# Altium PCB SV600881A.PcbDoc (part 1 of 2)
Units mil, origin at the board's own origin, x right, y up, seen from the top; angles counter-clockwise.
Board outline 3700 x 3510 mil, 4 copper layers (Top Layer, MidLayer1, MidLayer2, Bottom Layer), stack 62.2 mil thick; 110 components, 46 nets, 261 pads, 195 vias.
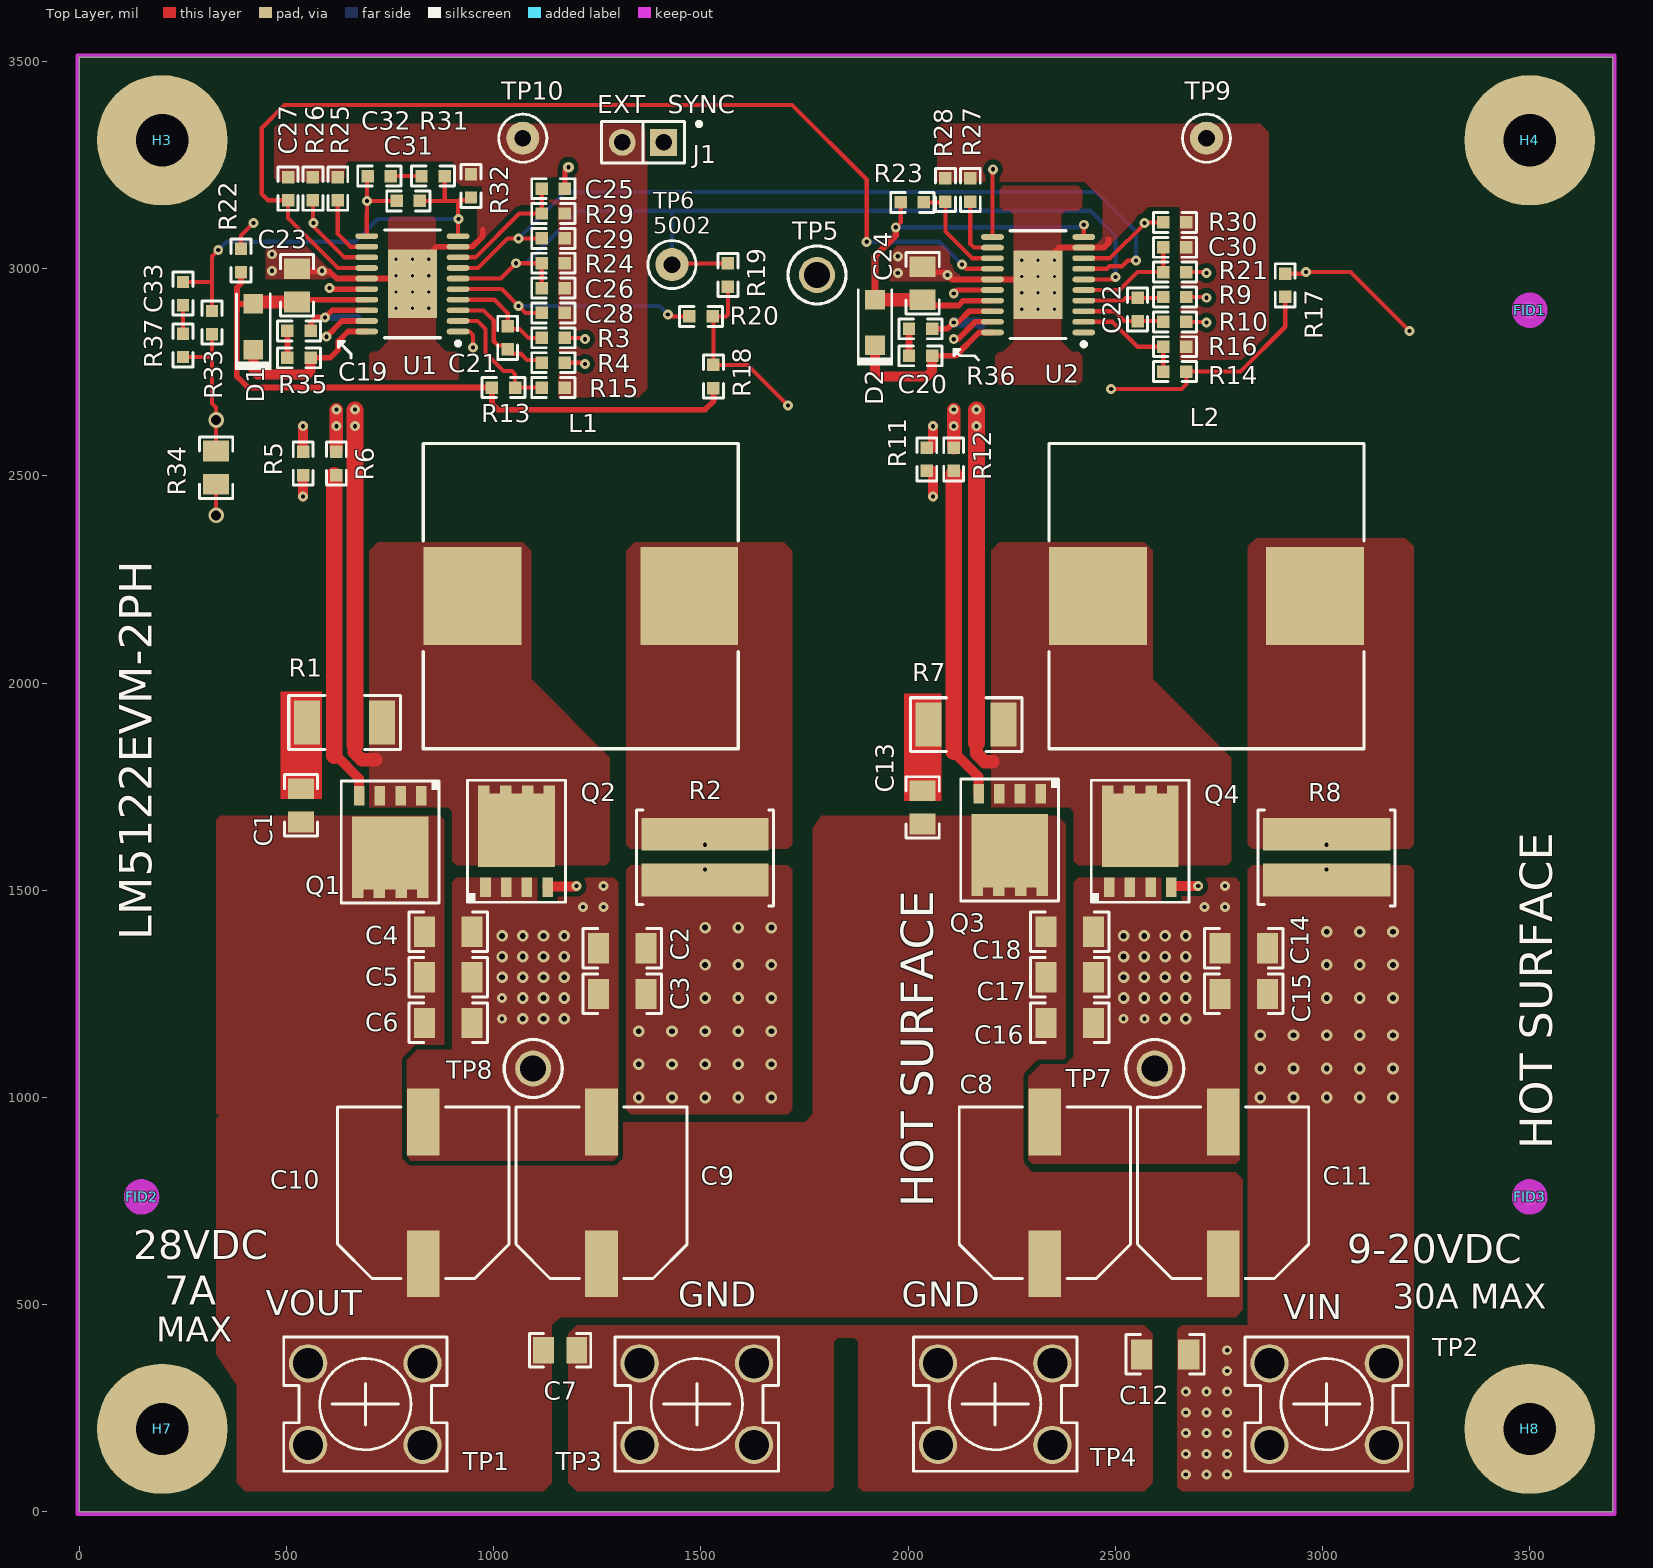
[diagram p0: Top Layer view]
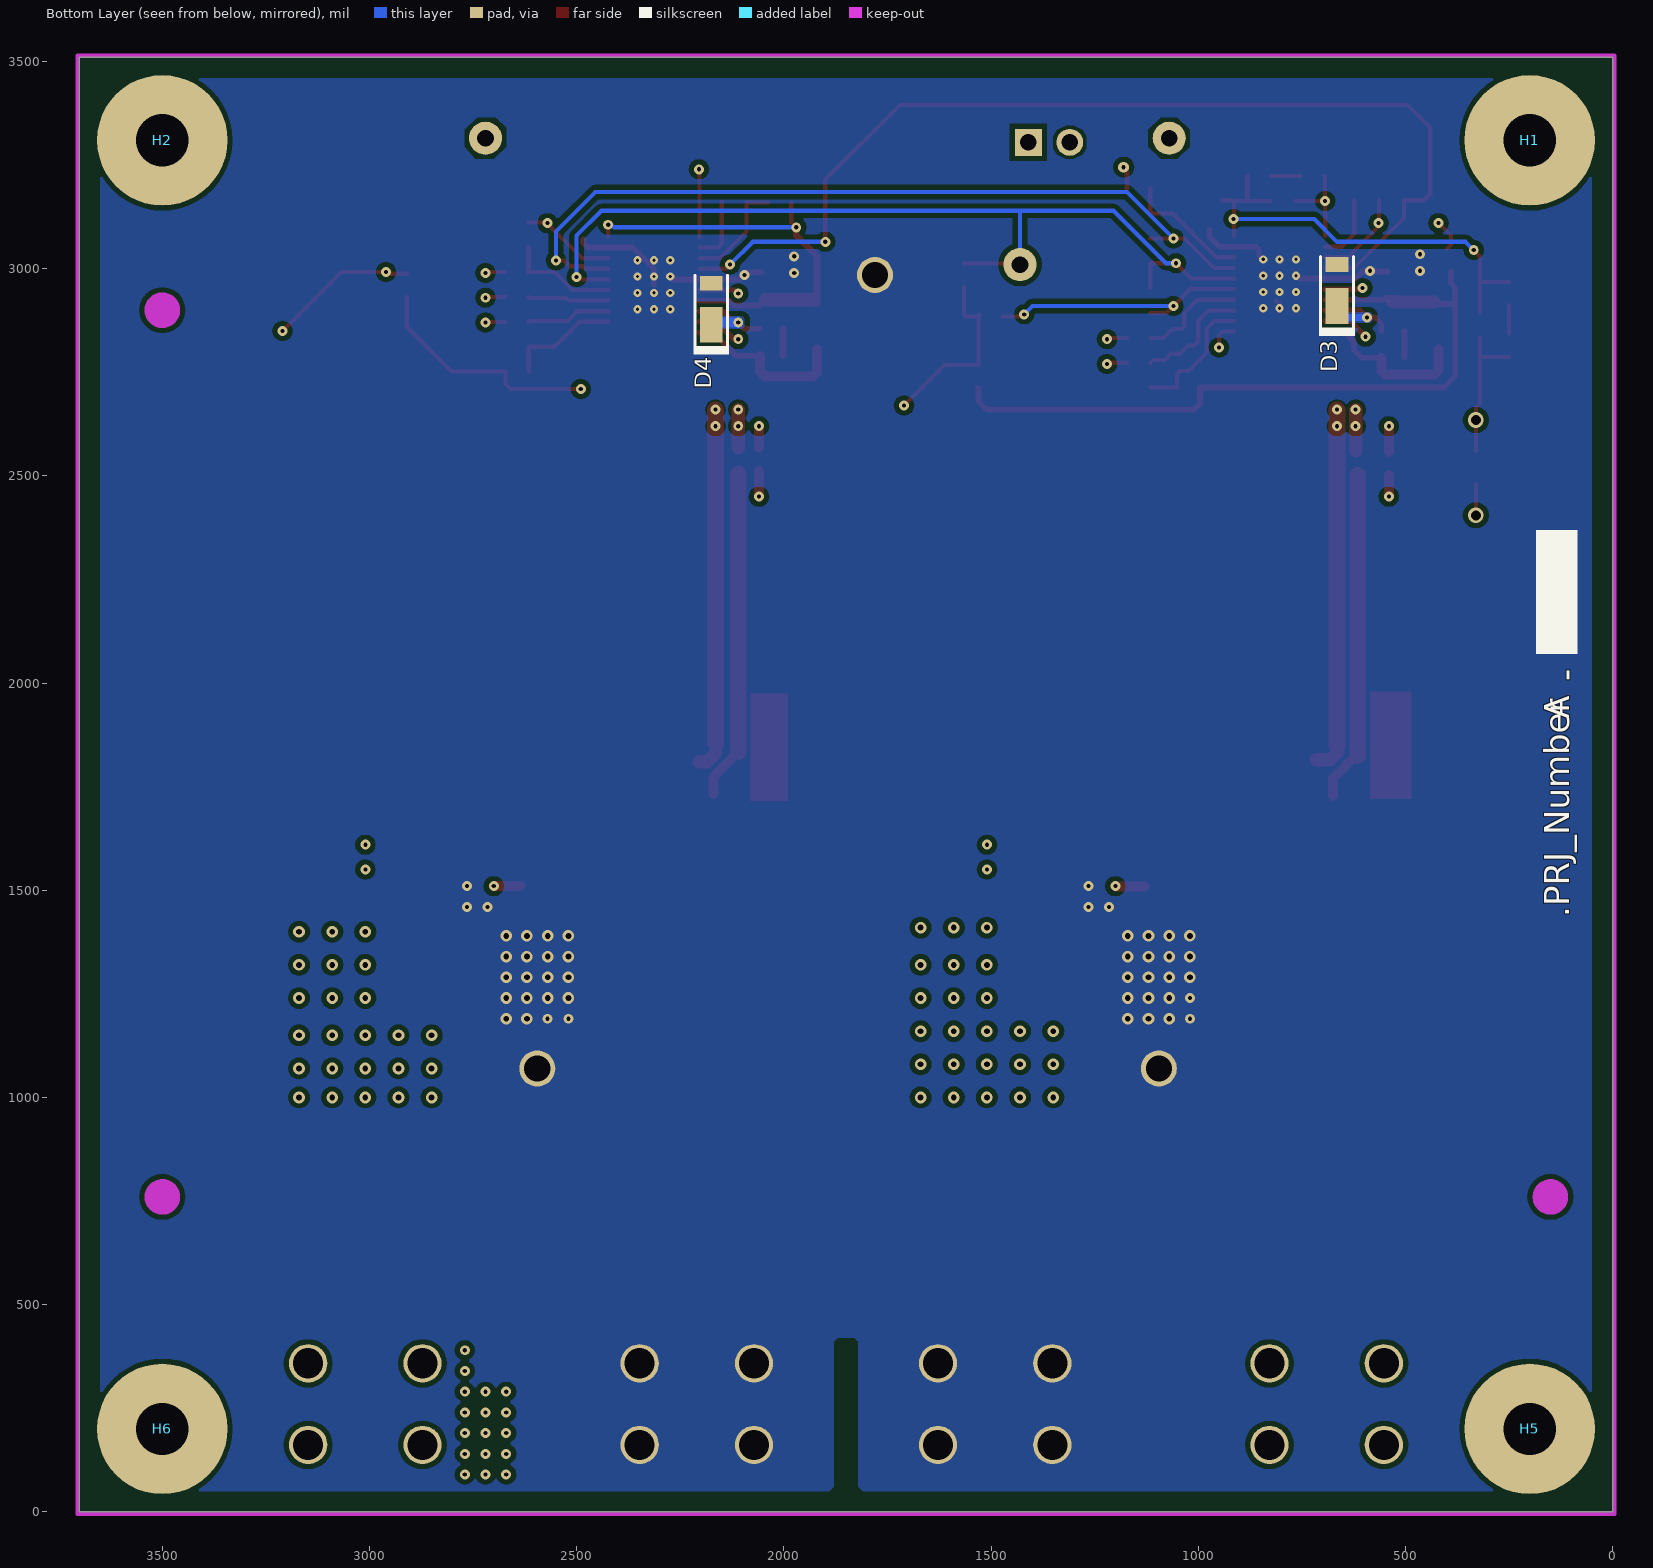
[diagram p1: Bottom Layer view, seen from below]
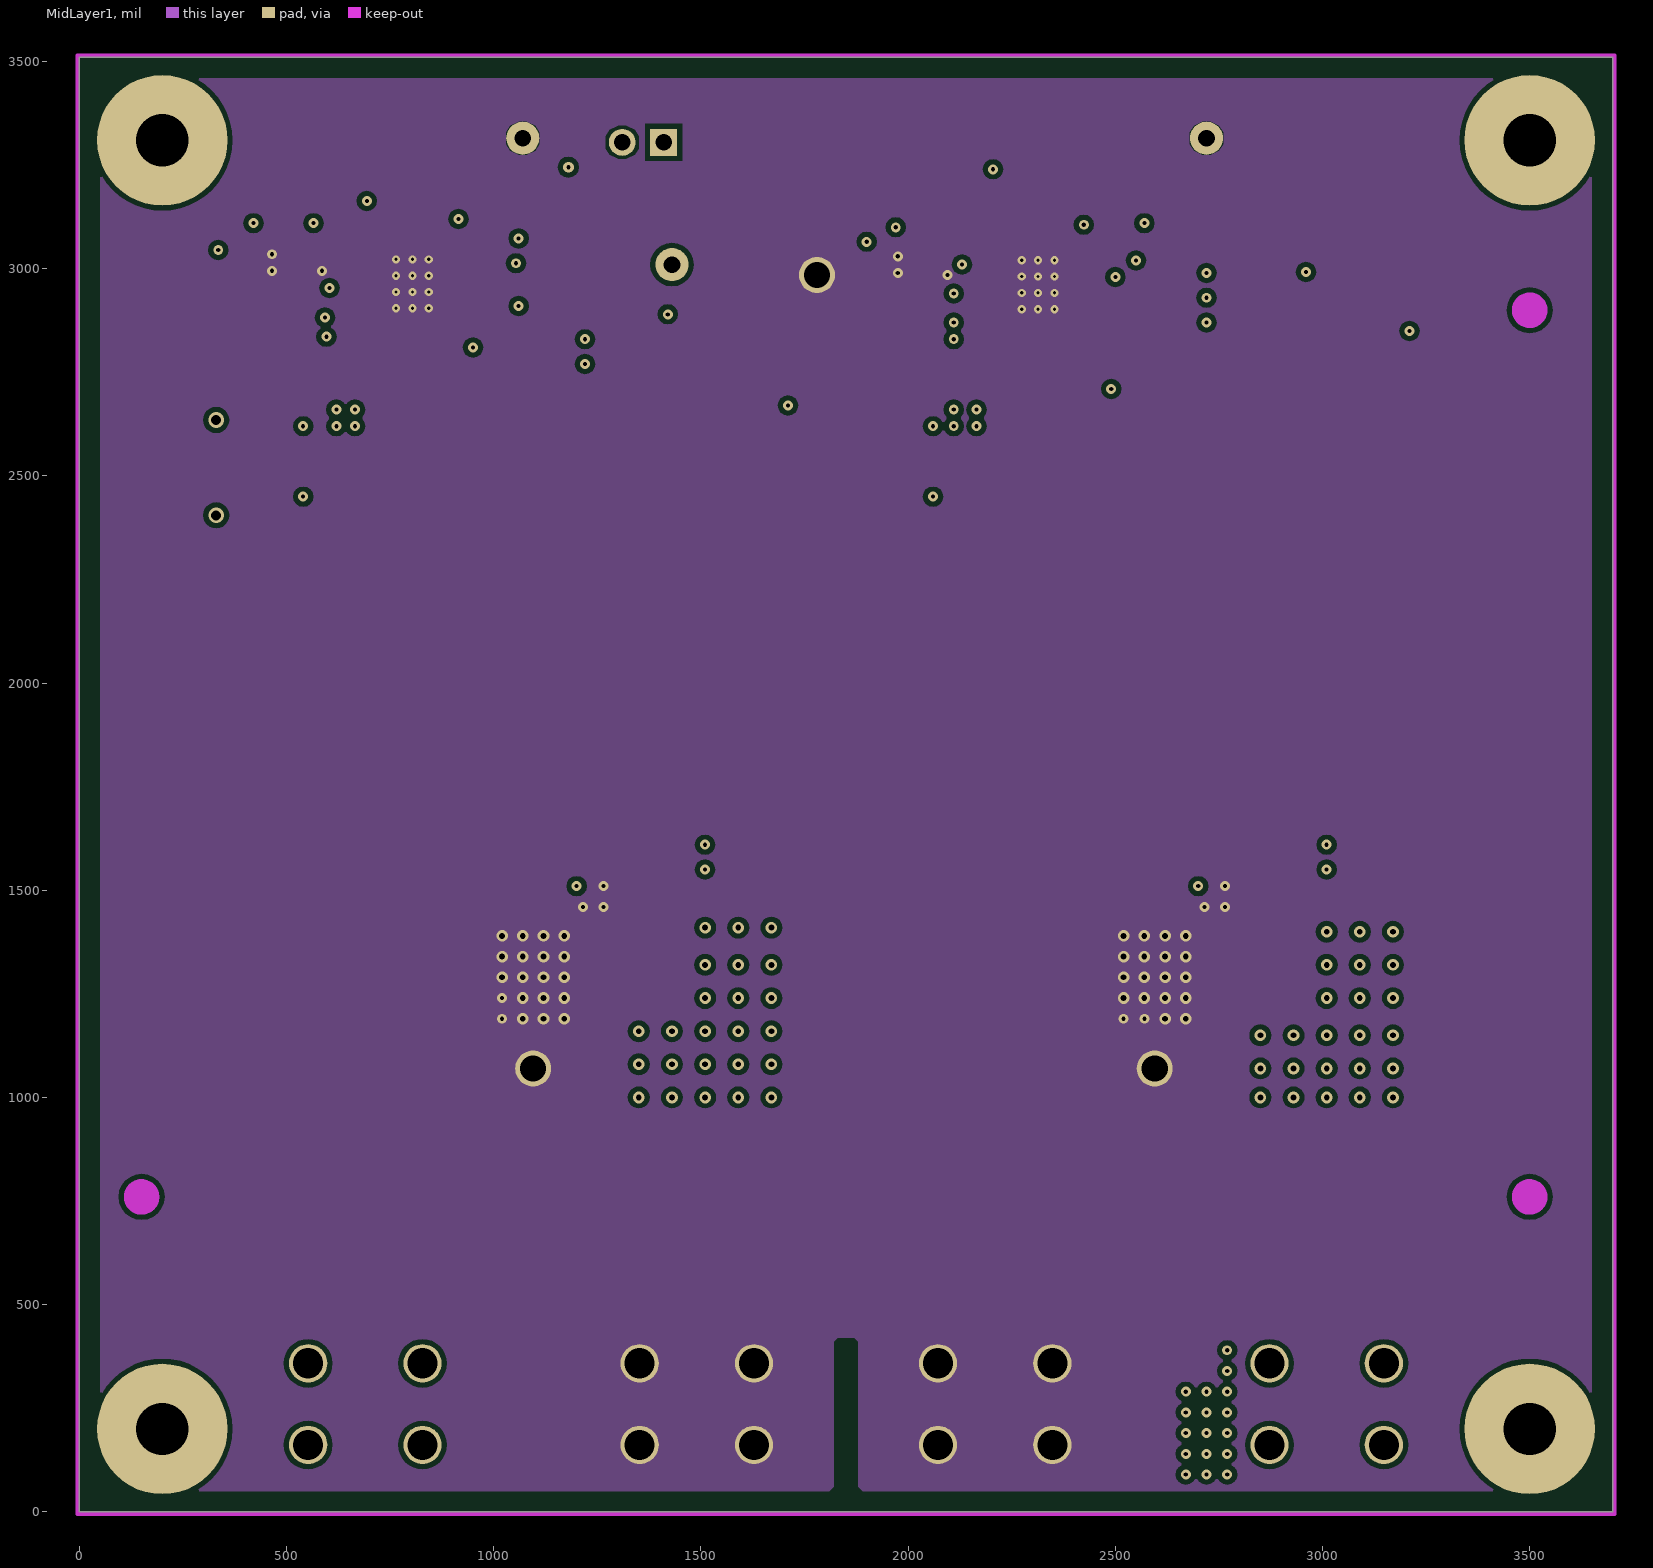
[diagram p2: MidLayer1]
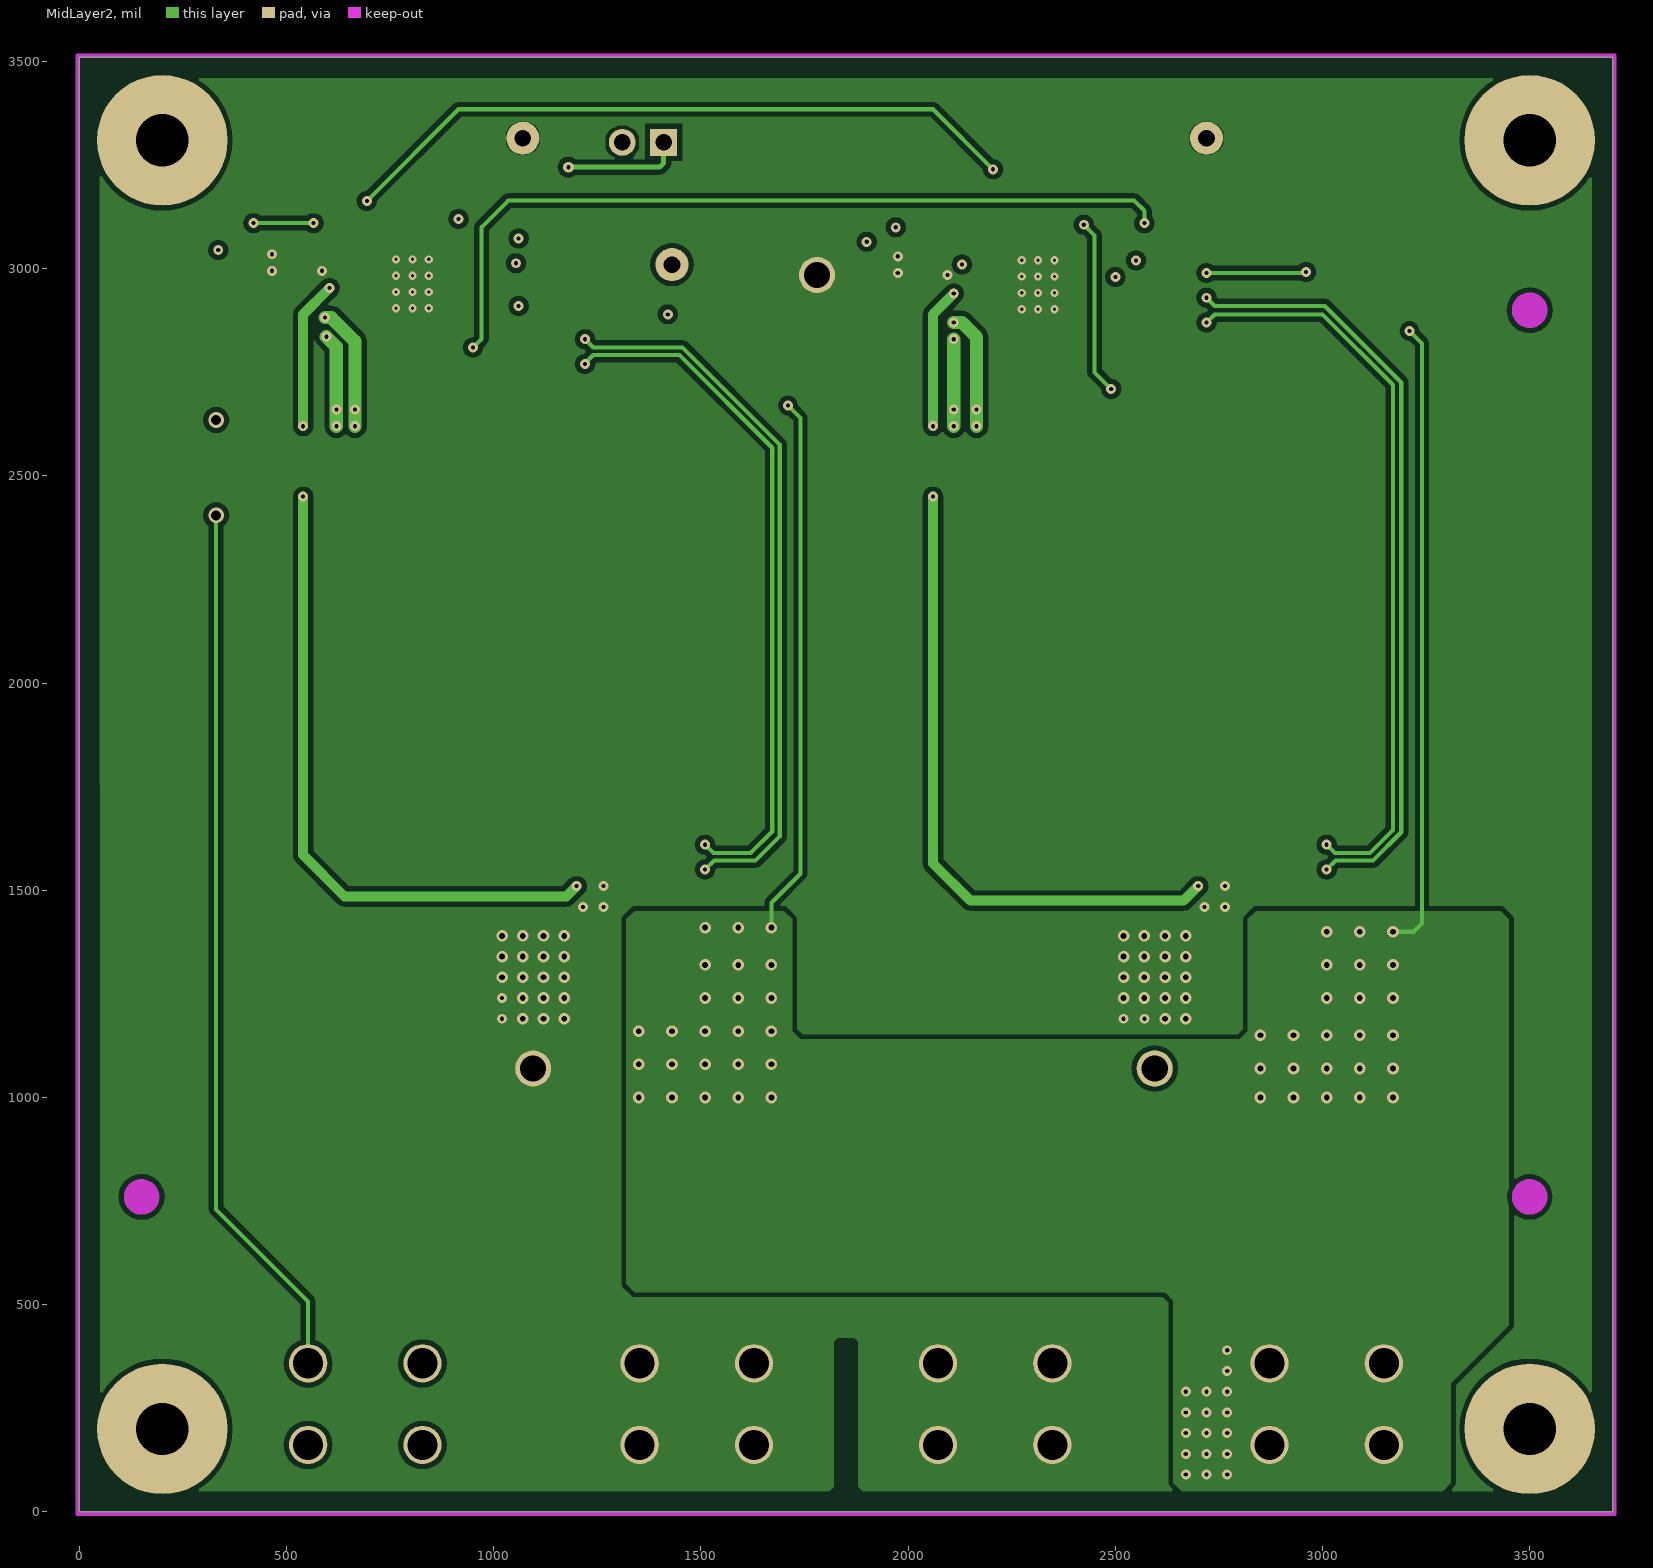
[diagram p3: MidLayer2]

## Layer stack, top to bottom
Top Solder: solder mask 0.4, Solder Resist, Dk 3.5
Top Layer: signal copper 2.8
Dielectric1: core 17, FR-4, Dk 4.8
MidLayer1: signal copper 2.8
Dielectric2: prepreg 17, FR-4, Dk 4.8
MidLayer2: signal copper 2.8
Dielectric3: core 17, FR-4, Dk 4.8
Bottom Layer: signal copper 2.8
Bottom Solder: solder mask 0.4, Solder Resist, Dk 3.5

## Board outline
0,0 0,3510 3700,3510 3700,0

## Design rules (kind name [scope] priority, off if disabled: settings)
AcuteAngle [All] p1: minimum=4.50000000000000E+0001 checktracksonly=FALSE
AssemblyTestPointUsage [All] p1: valid=2
Clearance Clearance_1 [IsRegion] p1: gap=12 ignorepadtopadclearanceinfootprint=FALSE except(0: Arc-Hole Track-Hole SMDPad-Hole THPad-Hole Via-Hole Fill-Hole Poly-Hole Region-Hole Text-Hole)
Clearance Clearance_BoardEdge_MountingHoles [OnCopper and InComponentClass('Mounting Holes') vs IsKeepOut] p2: gap=40 ignorepadtopadclearanceinfootprint=FALSE except(0: Arc-Hole Track-Hole SMDPad-Hole THPad-Hole Via-Hole Fill-Hole Poly-Hole Region-Hole Text-Hole)
Clearance Clearance_BoardEdge_Poly [OnCopper and InPoly vs IsKeepOut] p3: gap=25 ignorepadtopadclearanceinfootprint=FALSE except(0: Arc-Hole Track-Hole SMDPad-Hole THPad-Hole Via-Hole Fill-Hole Poly-Hole Region-Hole Text-Hole)
Clearance Clearance_BoardEdge [OnCopper and Not InComponentClass('Logo') and not InComponentClass('FiducialMark') and not InRegion(1000,500,4000,800) vs IsKeepOut] p4: gap=75 ignorepadtopadclearanceinfootprint=FALSE except(0: Arc-Hole Track-Hole SMDPad-Hole THPad-Hole Via-Hole Fill-Hole Poly-Hole Region-Hole Text-Hole)
Clearance [All] p5: gap=8 ignorepadtopadclearanceinfootprint=FALSE except(0: Arc-Hole Track-Hole SMDPad-Hole THPad-Hole Via-Hole Fill-Hole Poly-Hole Region-Hole Text-Hole)
ComponentClearance ComponentVOCap [HasFootprint('SM_RADIAL_G')] p1: gap=10 collisioncheckmode=3 verticalgap=10 showdistances=FALSE
ComponentClearance ComponentClearance_Logo [InComponentClass(Logo)] p2: gap=50 collisioncheckmode=3 verticalgap=10 showdistances=FALSE
ComponentClearance ComponentClearance_ScrewToNut [(HasFootprint('NY PMS 440 0025 PH')) vs (HasFootprint('Keystone_1902C'))] p3: gap=5 collisioncheckmode=3 verticalgap=10 showdistances=FALSE
ComponentClearance ComponentClearance_MountingHoles [InComponentClass('Mounting Holes')] p4: gap=150 collisioncheckmode=3 verticalgap=200 showdistances=FALSE
ComponentClearance ComponentClearance_SmallPassives [HasFootprint('0201*') or HasFootprint('0402*') or HasFootprint('0508') or HasFootprint('0603*') or HasFootprint('0612') or HasFootprint('0805*') or HasFootprint('0815*') or HasFootprint('0830*') or HasFootprint('1206*') or HasFootprint('1210*') or HasFootprint('1808*') or HasFootprint('1812*') or HasFootprint('1825*') or HasFootprint('2010*') or HasFootprint('2220*') or HasFootprint('2225*') or HasFootprint('2512*') or HasFootprint('2728*') or HasFootprint('3518*') vs HasFootprint('0201*') or HasFootprint('0402*') or HasFootprint('0508') or HasFootprint('0603*') or HasFootprint('0612') or HasFootprint('0805*') or HasFootprint('0815*') or HasFootprint('0830*') or HasFootprint('1206*') or HasFootprint('1210*') or HasFootprint('1808*') or HasFootprint('1812*') or HasFootprint('1825*') or HasFootprint('2010*') or HasFootprint('2220*') or HasFootprint('2225*') or HasFootprint('2512*') or HasFootprint('2728*') or HasFootprint('3518*')] p5: gap=20 collisioncheckmode=3 verticalgap=10 showdistances=FALSE
ComponentClearance ComponentClearance_THtoSMT [IsThruComponent vs IsSMTComponent] p6: gap=60 collisioncheckmode=3 verticalgap=60 showdistances=FALSE
ComponentClearance ComponentClearance_THtoTH [IsThruComponent vs IsThruComponent] p7: gap=60 collisioncheckmode=3 verticalgap=60 showdistances=FALSE
ComponentClearance [All] p8: gap=40 collisioncheckmode=3 verticalgap=10 showdistances=FALSE
DiffPairsRouting [All] p1: maxlimit=100 minlimit=10 mostfreqgap=10 toplayer_minwidth=15 toplayer_maxwidth=15 toplayer_prefwidth=15 midlayer1_minwidth=15 midlayer1_maxwidth=15 midlayer1_prefwidth=15 midlayer2_minwidth=15 midlayer2_maxwidth=15 midlayer2_prefwidth=15 bottomlayer_minwidth=15 bottomlayer_maxwidth=15 bottomlayer_prefwidth=15 maxuncoupledlength=1000
FabricationTestPointUsage TestPointUsage [All] p1: valid=2 allowmultiple=FALSE
FabricationTestpoint Testpoint [All] p1: side=3 testpointundercomponent=TRUE minsize=40 maxsize=100 preferedsize=60 minholesize=0 maxholesize=40 preferedholesize=32 testpointgrid=1 allowsidetop=TRUE allowsidebottom=TRUE usegrid=TRUE gridtolerance=0.01
FanoutControl Fanout_LCC [IsLCC] p1: bgadir=Out bgaviamode=Centered fanoutstyle=Auto fanoutdirection=Alternating viagrid=1 // Fanout_LCC (Default Rule)
FanoutControl Fanout_BGA [IsBGA] p2: bgadir=Out bgaviamode=Centered fanoutstyle=Auto fanoutdirection=Alternating viagrid=1 // Fanout_BGA (Default Rule)
FanoutControl Fanout_Default [All] p4: bgadir=Out bgaviamode=Centered fanoutstyle=Auto fanoutdirection=Alternating viagrid=1 // Fanout_Default (Default Rule)
FanoutControl Fanout_Small [(CompPinCount < 5)] p5: bgadir=Out bgaviamode=Centered fanoutstyle=Auto fanoutdirection=OutThenIn viagrid=1 // Fanout_Small (Default Rule)
HoleSize [All] p1: absolutevalues=TRUE maxlimit=251 minlimit=7.87 maxpercent=80.000 minpercent=20.000
MinimumAnnularRing MinimumAnnularRing_1 [HasFootprint('MXA20A_L')] p1: minimumring=5
MinimumAnnularRing [All] p2: minimumring=7
MinimumSolderMaskSliver MinimumSolderMaskSliver_Logo [InComponentClass('Logo') vs InComponentClass('Logo')] p1: minsoldermaskwidth=0.7
MinimumSolderMaskSliver [All] p2: minsoldermaskwidth=4
PlaneClearance PolygonClearance_1 [IsRegion] p1: clearance=10
PlaneClearance [All] p2: clearance=10
PlaneConnect [All] p1: planeconnectstyle=Relief reliefexpansion=10 reliefentries=4 reliefconductorwidth=10 reliefairgap=10
PolygonConnect [All] p1: connectstyle=Direct reliefconductorwidth=10 reliefentries=4 polygonreliefangle="90 Angle" airgapwidth=10
RoutingVias [All] p1: holewidth=10 width=24 viastyle="Through Hole" minholewidth=7 minwidth=14 maxholewidth=40 maxwidth=65
SMDToCorner [All] p1: distance=30000
SilkToSilkClearance [All] p1: silktosilkclearance=5
SilkToSolderMaskClearance SilkscreenOverComponentPads [IsPad] p1: minsilkscreentomaskgap=5 clearancetoexposedcopper=TRUE
SolderMaskExpansion [All] p1: expansion=3
Width [All] p1: maxlimit=100 minlimit=6 preferedwidth=10 checkconnectedcopper=TRUE
15 further rules are at their usual default settings.

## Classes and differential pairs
component class SV600881A_SH2: C19 C20 C21 C22 C23 C24 C25 C26 C27 C28 C29 C30 C31 C32 C33 D1 D2 D3 D4 J1 R13 R14 R15 R16 R17 R18 R19 R20 R21 R22 R23 R24 R25 R26 R27 R28 R29 R30 R31 R32 R33 R34 R35 R36 R37 TP5 TP6 TP9 TP10 U1 U2
component class SV600881A_SH1: C1 C2 C3 C4 C5 C6 C7 C8 C9 C10 C11 C12 C13 C14 C15 C16 C17 C18 L1 L2 Q1 Q2 Q3 Q4 R1 R2 R3 R4 R5 R6 R7 R8 R9 R10 R11 R12 SH1 TP1 TP2 TP3 TP4 TP7 TP8
component class FiducialMark: FID1 FID2 FID3
component class SV600881A_HW: FID1 FID2 FID3 H1 H2 H3 H4 H5 H6 H7 H8 ZZ1 ZZ2 ZZ3 ZZ4 ZZ5 ZZ6
component class "Mounting Holes": H3 H4 H7 H8
component class Header: J1
component class AssemblyNote: ZZ1 ZZ2 ZZ3 ZZ4 ZZ5 ZZ6

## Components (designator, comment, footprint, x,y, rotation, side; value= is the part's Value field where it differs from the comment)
C1 "GRM2165C2A471JA01D" 0805_HV 535,1705 r90 top value=470pF
C2 "3.3µF" 1206 1310,1360 r180 top
C3 "3.3µF" 1206 1310,1250 r180 top
C4 "10µF" 1206 890,1400 r0 top
C5 "10µF" 1206 890,1290 r0 top
C6 "10µF" 1206 890,1180 r0 top
C7 "GRM21BR71H105KA12L" 0805_HV 1160,390 r0 top value=1uF
C8 "EEE-FP1V331AP" SM_RADIAL_G 2330,770 r90 top value=330uF
C9 "EEE-FP1V331AP" SM_RADIAL_G 1260,770 r90 top value=330uF
C10 "EEE-FP1V331AP" SM_RADIAL_G 830,770 r90 top value=330uF
C11 "EEE-FP1V331AP" SM_RADIAL_G 2760,770 r90 top value=330uF
C12 "3.3µF" 1206 2620,380 r180 top
C13 "GRM2165C2A471JA01D" 0805_HV 2035,1700 r90 top value=470pF
C14 "3.3µF" 1206 2810,1360 r180 top
C15 "3.3µF" 1206 2810,1250 r180 top
C16 "10µF" 1206 2390,1180 r0 top
C17 "10µF" 1206 2390,1290 r0 top
C18 "10µF" 1206 2390,1400 r0 top
C19 "GRM188R71E104KA01D" 0603_HV 530,2785 r0 top value=0.1uF
C20 "GRM188R71E104KA01D" 0603_HV 2030,2790 r0 top value=0.1uF
C21 "GRM1885C1H101JA01D" 0603_HV 1033.6,2833.29 r90 top value=100pF
C22 "GRM1885C1H101JA01D" 0603_HV 2553.62,2901.81 r90 top value=100pF
C23 "GRM21BR71C475KA73L" 0805_HV 525,2960 r270 top value=4.7uF
C24 "GRM21BR71C475KA73L" 0805_HV 2035,2965 r270 top value=4.7uF
C25 "GRM1885C1H101JA01D" 0603_HV 1143.6,3193.29 r0 top value=100pF
C26 "GRM1885C1H101JA01D" 0603_HV 1143.6,2953.29 r0 top value=100pF
C27 "GRM188R71E474KA12D" 0603_HV 503.6,3193.29 r90 top value=0.47uF
C28 "GRM188R71E474KA12D" 0603_HV 1143.6,2893.29 r0 top value=0.47uF
C29 "GRM188R71E104KA01D" 0603_HV 1143.6,3073.29 r0 top value=0.1uF
C30 "GRM188R71E474KA12D" 0603_HV 2643.62,3051.81 r0 top value=0.47uF
C31 "C0603C331K5RACTU" 0603_HV 793.6,3163.6 r180 top value=330pF
C32 "C0603C223K5RACTU" 0603_HV 723.6,3223.6 r180 top value=0.022uF
C33 "NA" 0603_HV 250,2940 r90 top
D1 "PMEG6010CEH,115" SOD-123F 420,2860 r90 top value=0.57V
D2 "PMEG6010CEH,115" SOD-123F 1920,2870 r90 top value=0.57V
D3 "DFLS1100-7" powerDI123 665,2960 r90 bottom value=0.77V
D4 "DFLS1100-7" powerDI123 2175,2915 r90 bottom value=0.77V
FID1 "Fiducial" Fiducial10-20 3500,2900 r0 top
FID2 "Fiducial" Fiducial10-20 150,760 r0 top
FID3 "Fiducial" Fiducial10-20 3500,760 r0 top
H1 "1902C" Keystone_1902C 200,3310 r180 bottom locked
H2 "1902C" Keystone_1902C 3500,3310 r180 bottom locked
H3 "NY PMS 440 0025 PH" "NY PMS 440 0025 PH" 200,3310 r0 top locked
H4 "NY PMS 440 0025 PH" "NY PMS 440 0025 PH" 3500,3310 r0 top locked
H5 "1902C" Keystone_1902C 200,200 r180 bottom locked
H6 "1902C" Keystone_1902C 3500,200 r180 bottom locked
H7 "NY PMS 440 0025 PH" "NY PMS 440 0025 PH" 200,200 r0 top locked
H8 "NY PMS 440 0025 PH" "NY PMS 440 0025 PH" 3500,200 r0 top locked
J1 "TSW-102-07-G-S" TSW-102-07-G-S 1360,3305 r180 top
L1 "10uH" "WE-HCI 1890" 1210,2210 r180 top
L2 "10uH" "WE-HCI 1890" 2720,2210 r180 top
Q1 "PSMN4R0-40YS,115" PG-TDSON-8 750,1616.57 r270 top
Q2 "PSMN4R0-40YS,115" PG-TDSON-8 1055,1618.43 r90 top
Q3 "PSMN4R0-40YS,115" PG-TDSON-8 2245,1621.57 r270 top
Q4 "PSMN4R0-40YS,115" PG-TDSON-8 2560,1618.43 r90 top
R1 "8.2" 2010 640,1905 r180 top
R2 "0.004" KRL7638 1510,1580 r90 top
R3 "CRCW0603100RFKEA" 0603_HV 1143.6,2833.29 r0 top value=100
R4 "CRCW0603100RFKEA" 0603_HV 1143.6,2773.29 r0 top value=100
R5 "ERJ-3GEY0R00V" 0603_HV 540,2530 r90 top value=0
R6 "ERJ-3GEY0R00V" 0603_HV 620,2530 r270 top value=0
R7 "8.2" 2010 2140,1900 r180 top
R8 "0.004" KRL7638 3010,1580 r90 top
R9 "CRCW0603100RFKEA" 0603_HV 2643.62,2931.81 r0 top value=100
R10 "CRCW0603100RFKEA" 0603_HV 2643.62,2871.81 r0 top value=100
R11 "ERJ-3GEY0R00V" 0603_HV 2045,2540 r270 top value=0
R12 "ERJ-3GEY0R00V" 0603_HV 2110,2540 r90 top value=0
R13 "ERJ-3GEY0R00V" 0603_HV 1023.6,2713.29 r180 top value=0
R14 "ERJ-3GEY0R00V" 0603_HV 2643.62,2751.81 r0 top value=0
R15 "ERJ-3GEY0R00V" 0603_HV 1143.6,2713.29 r180 top value=0
R16 "ERJ-3GEY0R00V" 0603_HV 2643.62,2811.81 r180 top value=0
R17 "CRCW06033R30JNEA" 0603_HV 2910,2960 r90 top value=3.3
R18 "CRCW06033R30JNEA" 0603_HV 1530,2740 r270 top value=3.3
R19 "CRCW060349K9FKEA" 0603_HV 1565,2985 r270 top value=49.9k
R20 "CRCW06033R30JNEA" 0603_HV 1500,2885 r0 top value=3.3
R21 "CRCW06033R30JNEA" 0603_HV 2643.62,2991.81 r0 top value=3.3
R22 "ERJ-3GEY0R00V" 0603_HV 390,3020 r270 top value=0
R23 "ERJ-3GEY0R00V" 0603_HV 2010,3160 r180 top value=0
R24 "CRCW06038K06FKEA" 0603_HV 1143.6,3013.29 r180 top value=8.06k
R25 "CRCW060378K7FKEA" 0603_HV 623.6,3193.29 r270 top value=78.7k
R26 "ERJ-3GEY0R00V" 0603_HV 563.6,3193.29 r270 top value=0
R27 "CRCW060378K7FKEA" 0603_HV 2150,3190 r270 top value=78.7k
R28 "ERJ-3GEY0R00V" 0603_HV 2090,3190 r270 top value=0
R29 "CRCW060336K5FKEA" 0603_HV 1143.6,3133.29 r180 top value=36.5k
R30 "CRCW060340K2FKEA" 0603_HV 2643.62,3111.81 r180 top value=40.2k
R31 "CRCW060359K0FKEA" 0603_HV 853.6,3223.6 r180 top value=59.0k
R32 "CRCW06032K26FKEA" 0603_HV 945,3200 r90 top value=2.26k
R33 "CRCW060349K9FKEA" 0603_HV 320,2870 r270 top value=49.9k
R34 "CRCW0805576RFKEA" 0805_HV 330,2520 r90 top value=576
R35 "ERJ-3GEY0R00V" 0603_HV 530,2850 r180 top value=0
R36 "ERJ-3GEY0R00V" 0603_HV 2030,2855 r180 top value=0
R37 "NA" 0603_HV 250,2815 r270 top
TP1 "7693" 7693 690,260 r270 top value=15A
TP2 "7693" 7693 3010,260 r270 top value=15A
TP3 "7693" 7693 1490,260 r270 top value=15A
TP4 "7693" 7693 2210,260 r270 top value=15A
TP5 "5011" Keystone5011 1780,2985 r90 top value=Black
TP6 "5002" Keystone5002 1430,3010 r90 top value=White
TP7 "5011" Keystone5011 2595,1070 r0 top value=Black
TP8 "5011" Keystone5011 1095,1070 r90 top value=Black
TP9 "5001" Keystone5001 2720,3315 r90 top value=Black
TP10 "5001" Keystone5001 1070,3315 r90 top value=Black
U1 "LM5122MH" MXA20A_L 803.6,2963.6 r180 top
U2 "LM5122MH" MXA20A_L 2313.62,2961.5 r180 top
ZZ1 "ASSEMBLY NOTES:" AssemblyNoteLabel 4790,3480 r0 top
ZZ2 "These assemblies must be clean and free from flux and all contaminents.  Use of no clean flux is not acceptable." AssemblyNote 4790,3127.8 r0 top
ZZ3 "These Assemblies are ESD sensitive,  ESD precautions shall be observed." AssemblyNote 4790,3293.74 r0 top
ZZ4 "These assemblies must comply with workmanship standards IPC-A-610 class 2, unless otherwise specified." AssemblyNote 4790,2961.87 r0 top
ZZ5 "Standoffs shall be mounted on the bottom side of the assembly." AssemblyNote 4790,2795.93 r0 top
ZZ6 "Test point TP1- TP11, UVLO test pin, and J1 shall be mounted on top (component) side of PCB." AssemblyNote 4790,2630 r0 top

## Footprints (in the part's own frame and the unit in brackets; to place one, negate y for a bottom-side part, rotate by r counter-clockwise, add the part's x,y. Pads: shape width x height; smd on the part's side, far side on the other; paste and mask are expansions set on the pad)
0603_HV [mil] "Ernesto recommended land pattern.  26 mil between pads."
  rect 30x30 smd: 1(-28,0) 2(28,0)
  silkscreen extent -52,-24 52,24, body extent -34,-19 34,19, height 33
0805_HV [mil] "0805 with 30mil clearance between pads"
  rect 50x63 smd: 1(-40,0) 2(40,0)
  silkscreen extent -74,-40 74,40, body extent -43,-29 43,29, height 43
1206 [mm] "1206 from SM-752 data"
  rect 1.3x1.85 smd: 1(-1.45,0) 2(1.45,0)
  silkscreen extent -2.4,-1.21 2.4,1.21, body extent -1.7,-0.9 1.7,0.9, height 1.35
2010 [mm] "Chip Capacitor, Body 5.08x2.54mm, IPC Medium Density"
  rect 1.6x2.7 smd: 1(-2.3,0) 2(2.3,0)
  silkscreen extent -3.42,-1.65 3.42,1.65, body extent -2.73,-1.45 2.73,1.45, height 1.66
7693 [mm] "Keystone Electronics 7693 recommended land pattern"
  round 2.35 hole 1.85: 1(-2.502,3.505) 2(2.502,3.505) 3(-2.502,-3.505) 4(2.502,-3.505)
  silkscreen extent -4.11,-5 4.11,5, body extent -3.95,-3.94 3.95,3.96, height 8.86
AssemblyNote [mil] "Assembly Note"
AssemblyNoteLabel [mil] "Assembly Note for PCB Labels"
Fiducial10-20 [mm]
  round 1 smd paste-0.5 mask+0.5: 1(0,0)
  Keep-Out Layer circle w1.178: c0,0 r0.5
Keystone5001 [mil] "For Keystone 500x miniature loop terminals"
  round 80 hole 40: 1(0,0)
  silkscreen extent -58,-58 58,58, body extent -49,-49 49,49, height 182
Keystone5002 [mil] "For Keystone 500x miniature loop terminals"
  round 80 hole 40: 1(0,0)
  silkscreen extent -58,-58 58,58, body extent -49,-49 49,49, height 182
Keystone5011 [mil] "Keystone Multipurpose loops"
  round 87 hole 63: 1(0,0)
  silkscreen extent -70,-70 70,70, body extent -63,-63 63,62, height 319
Keystone_1902C [mil] "Hex Standoff, 4-40 threaded, nylon"
  body extent -145,-126 146,126, height 501
KRL7638 [mm] "Chip Resistor, 2-Leads, Body 3.8x7.6mm, IPC Low Density based on Susumu KRL7628W dimensions."
  rect 2x7.8 smd: 1(-1.4,0) 2(1.4,0)
  silkscreen extent -3,-4.2 2.9,4.2, body extent -1.8,-3.9 1.8,3.9, height 0.7
MXA20A_L [mm] "TSOP, 20-Leads, Body 6.5x4.4mm, Pitch 0.65mm, Exposed Pad, IPC High Density"
  oval 1.4x0.35 smd: 1(-2.8,2.925) 2(-2.8,2.275) 3(-2.8,1.625) 4(-2.8,0.975) 5(-2.8,0.325) 6(-2.8,-0.325) 7(-2.8,-0.975) 8(-2.8,-1.625) 9(-2.8,-2.275) 10(-2.8,-2.925) 11(2.8,-2.925) 12(2.8,-2.275) 13(2.8,-1.625) 14(2.8,-0.975) 15(2.8,-0.325) 16(2.8,0.325) 17(2.8,0.975) 18(2.8,1.625) 19(2.8,2.275) 20(2.8,2.925)
  rect 3x4.2 smd: 21(0,0)
  silkscreen extent -2.93,-3.3 1.7,3.77, body extent -2.25,-3.3 2.25,3.3, height 1.1
"NY PMS 440 0025 PH" [mm] "4-40 nylon screw and mounting hole"
  round 8 hole 3.2: 1(0,0)
  body extent -3.3,-3.3 3.3,3.3, height 2.69
PG-TDSON-8 [mm] "Infineon recommended land pattern"
  rect 1.2x0.65 smd: 1(-2.825,1.905) 2(-2.825,0.635) 3(-2.825,-0.635) 4(-2.825,-1.905)
  rect 0.5x0.7 smd: 5(3.175,-2) 6(3.175,-0.675) 7(3.175,0.675) 8(3.175,2)
  rect 4.5x4.7 smd paste-2.25: 9(0.675,0)
  silkscreen extent -3.74,-3 3.74,3, body extent -3.18,-2.89 3.18,2.9, height 1.1
powerDI123 [mm] "Diodes Inc recommended land pattern, document number DS30628 Rev. 6-2"
  rect 2.2x1.4 smd: 1(-1.275,0)
  rect 0.9x1.4 smd: 2(1.275,0)
  silkscreen extent -3.1,-1.09 1.76,1.09, body extent -2.37,-0.96 1.53,0.97, height 1
SM_RADIAL_G [mm] "10 x 10.2mm:  Panasonic G"
  rect 4.1x2 smd: 1(-4.35,0) 2(4.35,0)
  silkscreen extent -5.25,-5.25 5.25,5.25, body extent -5.25,-5.25 5.25,5.25, height 10.5
SOD-123F [mm] "NXP recommended land pattern"
  rect 1.2x1.2 smd paste-0.05: 1(-1.4,0) 2(1.4,0)
  silkscreen extent -2.64,-1.12 2.01,1.12, body extent -1.8,-0.85 1.8,0.85, height 1.2
TSW-102-07-G-S [mm] "Samtec 100mil, 1x2, 230 mil above insulator"
  rect 1.65x1.65 hole 1.016 mask+0: 1(-1.27,0)
  round 1.65 hole 1.016 mask+0: 2(1.27,0)
  silkscreen extent -3.57,-1.27 2.54,1.27, body extent -2.54,-1.27 2.54,1.27, height 8.38
"WE-HCI 1890" [mm] "Inductor, 2-Leads, Body 18,3x18,2mm"
  rect 6x6 smd: 1(-6.65,0) 2(6.65,0)
  silkscreen extent -9.65,-9.35 9.65,9.35, body extent -9.15,-9.1 9.15,9.1, height 8.85

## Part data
C1 C13: "CAP, CERM, 470pF, 100V, +/-5%, C0G/NP0, 0805", Alternate Manufacturer=-, Cap_Case=0805, Manufacturer=MuRata, Supplier Part Number 1=490-1611-1-ND, TempCo=C0G/NP0, Tolerance_%=5, Value1=?, Value2=100V, ValueDisplayed=470pF
C2 C3 C12 C14 C15: library part C3216X7R1H335K160AC, "CAP CER 3.3UF 50V 10% X7R 1206", Alternate Manufacturer=-, Manufacturer="TDK Corporation", Operating Temperature="-55°C ~ 125°C", Supplier Part Number 1=445-5990-1-ND, TempCo=X7R, Tolerance_%=±10%
C4 C5 C6 C16 C17 C18: library part GMK316AB7106KL-TR, "CAP CER 10UF 35V 10% X7R 1206", Alternate Manufacturer=-, Manufacturer="Taiyo Yuden", Operating Temperature="-55°C ~ 125°C", Supplier Part Number 1=587-3007-1-ND, TempCo=X7R, Tolerance_%=±10%
C7: "CAP, CERM, 1uF, 50V, +/-10%, X7R, 0805", Alternate Manufacturer=-, Cap_Case=0805, Manufacturer=MuRata, Supplier Part Number 1=490-4736-1-ND, TempCo=X7R, Tolerance_%=10, Value1=?, Value2=50V, ValueDisplayed=1µF
C8 C9 C10 C11: "CAP ALUM 330UF 35V 20% SMD", Alternate Manufacturer=-, Cap_Case=G, Manufacturer=Panasonic, Supplier Part Number 1=PCE4445CT-ND, Tolerance_%=20, Value1="0.06 ohm", Value2=35V, ValueDisplayed=330µF
C19 C20 C29: "CAP, CERM, 0.1uF, 25V, +/-10%, X7R, 0603", Alternate Manufacturer=-, Cap_Case=0603, Manufacturer=MuRata, Supplier Part Number 1=490-1524-1-ND, TempCo=X7R, Tolerance_%=10, Value1=?, Value2=25V, ValueDisplayed=0.1µF
C21 C22 C25 C26: "CAP, CERM, 100pF, 50V, +/-5%, C0G/NP0, 0603", Alternate Manufacturer=-, Cap_Case=0603, Manufacturer=MuRata, Supplier Part Number 1=490-1427-1-ND, TempCo=C0G/NP0, Tolerance_%=5, Value1=?, Value2=50V, ValueDisplayed=100pF
C23 C24: "CAP, CERM, 4.7uF, 16V, +/-10%, X7R, 0805", Alternate Manufacturer=-, Cap_Case=0805, Manufacturer=MuRata, Supplier Part Number 1=490-4522-1-ND, TempCo=X7R, Tolerance_%=10, Value1="0.006 ohm", Value2=16V, ValueDisplayed=4.7µF
C27 C28 C30: "CAP, CERM, 0.47uF, 25V, +/-10%, X7R, 0603", Alternate Manufacturer=-, Cap_Case=0603, Manufacturer=MuRata, Supplier Part Number 1=490-3291-1-ND, TempCo=X7R, Tolerance_%=10, Value1=?, Value2=25V, ValueDisplayed=0.47µF
C31: "CAP, CERM, 330pF, 50V, +/-10%, X7R, 0603", Alternate Manufacturer=-, Cap_Case=0603, Manufacturer=Kemet, Supplier Part Number 1=399-1073-1-ND, TempCo=X7R, Tolerance_%=10, Value1=?, Value2=50V, ValueDisplayed=330pF
C32: "CAP, CERM, 0.022uF, 50V, +/-10%, X7R, 0603", Alternate Manufacturer=-, Cap_Case=0603, Manufacturer=Kemet, Supplier Part Number 1=399-1280-1-ND, TempCo=X7R, Tolerance_%=10, Value1=?, Value2=50V, ValueDisplayed=0.022µF
C33: library part Capacitor, "CAP, CERM, xxxF, xxV, [TempCo], xx%, [PackageReference]", Alternate Manufacturer=-, Manufacturer="Used in BOM report"
D1 D2: "Diode, Schottky, 60V, 1A, SOD-123F", Alternate Manufacturer=-, Manufacturer="NXP Semiconductor", Supplier Part Number 1=568-4104-1-ND, Value1=1A, Value2=60V
D3 D4: "Diode, Schottky, 100V, 1A, PowerDI123", Alternate Manufacturer=-, Manufacturer="Diodes Inc.", Supplier Part Number 1=DFLS1100DICT-ND, Value1=1A, Value2=100V
FID1 FID2 FID3: "Fiducial mark.  There is nothing to buy or mount.", Manufacturer=N/A
H1 H2 H5 H6: "Standoff, Hex, 0.5\"L #4-40 Nylon", Alternate Manufacturer=-, Manufacturer=Keystone, Supplier Part Number 1=1902CK-ND
H3 H4 H7 H8: "Machine Screw, Round, #4-40 x 1/4, Nylon, Philips panhead", Alternate Manufacturer=-, DigiKeyPartNumber=H542-ND, Manufacturer="B&F Fastener Supply"
J1: "Header, TH, 100mil, 2x1, Gold plated, 230 mil above insulator", Alternate Manufacturer=-, Manufacturer="Samtec, Inc.", Supplier Part Number 1=SAM1029-02-ND
L1 L2: library part "WE-HCI 1890, 74435561100", "SMD Flat Wire High Current Inductor WE-HCI, L=10.0 µH", Inductance="10.0 µH", PartNumber=74435561100, Supplier Part Number 1=732-2167-1-ND
Q1 Q2 Q3 Q4: "MOSFET N-CH 40V 100A LFPAK", Alternate Manufacturer=-, Input Capacitance (Ciss) @ Vds="2410pF @ 20V", Manufacturer="NXP Semiconductors", Power - Max=106W, Supplier Device Package="LFPAK, Power-SO8", Supplier Part Number 1=568-4905-1-ND
R1 R7: library part CRCW20108R20JNEF, "RES 8.2 OHM 3/4W 5% 2010 SMD", Alternate Manufacturer=-, Manufacturer="Vishay Dale", Power_W="0.75W, 3/4W", Supplier Device Package="2010 (5025 Metric)", Supplier Part Number 1=541-8.2WCT-ND, TempCo=±200ppm/°C, Tolerance_%=±5%
R2 R8: library part KRL7638-C-R004, "RES, 0.004 OHM, 3W, 1%, 3015, WIDE", Alternate Manufacturer=Ohmite, Alternate PartNumber=FCSL76R004FER, Manufacturer=Susumu, PartNumber=KRL7638-C-R004-F-T1, Power_W=3W, Supplier Part Number 1=KRL76C.004CT-ND, TempCo=±50ppm/°C, Tolerance_%=±1%
R3 R4 R9 R10: "RES, 100 ohm, 1%, 0.1W, 0603", Alternate Manufacturer=Any, Alternate PartNumber=Equivalent, Manufacturer=Vishay-Dale, Power_W=0.1, Supplier Part Number 1=541-100HCT-ND, TempCo="100 ppm/C", Tolerance_%=1, Value1=1%, Value2=0.1W, Value_Code=100R
R5 R6 R11 R12 R13 R14 R15 R16 R22 R23 R26 R28 R35 R36: "RES, 0 ohm, 5%, 0.1W, 0603", Alternate Manufacturer=-, Manufacturer=Panasonic, Power_W=0.1, Supplier Part Number 1=P0.0GCT-ND, TempCo="600 ppm/C", Tolerance_%=5, Value1=5%, Value2=0.1W, Value_Code=0000
R17 R18 R20 R21: "RES, 3.3 ohm, 5%, 0.1W, 0603", Alternate Manufacturer=-, Manufacturer=Vishay-Dale, Power_W=0.1, Supplier Part Number 1=541-3.3GCT-ND, TempCo="200 ppm/C", Tolerance_%=5, Value1=5%, Value2=0.1W, Value_Code=3R30
R19 R33: "RES, 49.9k ohm, 1%, 0.1W, 0603", Alternate Manufacturer=-, Manufacturer=Vishay-Dale, Power_W=0.1, Supplier Part Number 1=541-49.9KHCT-ND, TempCo="100 ppm/C", Tolerance_%=1, Value1=1%, Value2=0.1W, Value_Code=49k9
R24: "RES, 8.06k ohm, 1%, 0.1W, 0603", Alternate Manufacturer=Any, Alternate PartNumber=Equivalent, Manufacturer=Vishay-Dale, Power_W=0.1, Supplier Part Number 1=541-8.06KHCT-ND, TempCo="100 ppm/C", Tolerance_%=1, Value1=1%, Value2=0.1W, Value_Code=8k06
R25 R27: "RES, 78.7k ohm, 1%, 0.1W, 0603", Alternate Manufacturer=Any, Alternate PartNumber=Equivalent, Manufacturer=Vishay-Dale, Power_W=0.1, Supplier Part Number 1=541-78.7KHCT-ND, TempCo="100 ppm/C", Tolerance_%=1, Value1=1%, Value2=0.1W, Value_Code=78k7
R29: "RES, 36.5k ohm, 1%, 0.1W, 0603", Alternate Manufacturer=Any, Alternate PartNumber=Equivalent, Manufacturer=Vishay-Dale, Power_W=0.1, Supplier Part Number 1=541-36.5KHCT-ND, TempCo="100 ppm/C", Tolerance_%=1, Value1=1%, Value2=0.1W, Value_Code=36k5
R30: "RES, 40.2k ohm, 1%, 0.1W, 0603", Alternate Manufacturer=-, Manufacturer=Vishay-Dale, Power_W=0.1, Supplier Part Number 1=541-40.2KHCT-ND, TempCo="100 ppm/C", Tolerance_%=1, Value1=1%, Value2=0.1W, Value_Code=40k2
R31: "RES, 59.0k ohm, 1%, 0.1W, 0603", Alternate Manufacturer=-, Manufacturer=Vishay-Dale, Power_W=0.1, Supplier Part Number 1=541-59.0KHCT-ND, TempCo="100 ppm/C", Tolerance_%=1, Value1=1%, Value2=0.1W, Value_Code=59k0
R32: "RES, 2.26k ohm, 1%, 0.1W, 0603", Alternate Manufacturer=-, Manufacturer=Vishay-Dale, Power_W=0.1, Supplier Part Number 1=541-2.26KHCT-ND, TempCo="100 ppm/C", Tolerance_%=1, Value1=1%, Value2=0.1W, Value_Code=2k26
R34: "RES, 576 ohm, 1%, 0.125W, 0805", Alternate Manufacturer=Any, Alternate PartNumber=Equivalent, Manufacturer=Vishay-Dale, Power_W=0.125, Supplier Part Number 1=541-576CCT-ND, TempCo="100 ppm/C", Tolerance_%=1, Value1=1%, Value2=0.125W, Value_Code=576R
R37: library part Resistor, "RES, xxx ohm, x%, xW, [PackageReference]", Alternate Manufacturer=-, Manufacturer="Used in BOM report"
TP1 TP2 TP3 TP4: "Terminal screw, vertical, snap-in", Alternate Manufacturer=-, DigiKeyPartNumber=7693K-ND, Manufacturer=Keystone
TP5 TP7 TP8: "Test Point, TH, Multipurpose, Black", Alternate Manufacturer=-, DigiKeyPartNumber=5011K-ND, Manufacturer=Keystone
TP6: "Test Point, TH, Miniature, White", Alternate Manufacturer=-, DigiKeyPartNumber=5002K-ND, Manufacturer=Keystone
TP9 TP10: "Test Point, TH, Miniature, Black", Alternate Manufacturer=-, DigiKeyPartNumber=5001K-ND, Manufacturer=Keystone
U1 U2: library part LM5122, Alternate Manufacturer=-, Manufacturer=TI
ZZ1: library part AssemblyNoteLabel, Alternate Manufacturer=-
ZZ2 ZZ3 ZZ4 ZZ5 ZZ6: library part AssemblyNote, Alternate Manufacturer=-

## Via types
v1: diameter 24, hole 10, Top Layer to Bottom Layer, 84 vias
v2: diameter 28, hole 14, Top Layer to Bottom Layer, 84 vias
v3: diameter 19.68, hole 7.87, Top Layer to Bottom Layer, 24 vias
v4: diameter 38, hole 24, Top Layer to Bottom Layer, 2 vias
v5: diameter 26, hole 10, Top Layer to Bottom Layer, 1 vias

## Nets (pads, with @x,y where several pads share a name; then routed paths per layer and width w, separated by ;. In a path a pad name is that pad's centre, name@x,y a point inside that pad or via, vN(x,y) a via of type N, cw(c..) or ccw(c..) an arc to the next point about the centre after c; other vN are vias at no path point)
COMP: C31.2 C32.2 U1.11 U2.11 | length 2046.4
  Top Layer w10: U1.11@693.37,3078.76 693.37,3133.37 693.6,3133.6 v1@693.6,3160 ; C32.2@695.6,3223.6 693.6,3221.6 v1(693.6,3163.6) C31.2@765.6,3163.6 ; U2.11@2203.39,3076.65 2203.39,3238.39 v1(2205,3240)
  MidLayer2 w10: v1@690,3160 v1(693.6,3163.6) 915,3385 2060,3385 v1(2205,3240)
EXT_SYNC: C25.2 J1.1 | length 339.3
  Top Layer w12: C25.2@1171.6,3193.29 1171.6,3236.6 v5(1180,3245)
  MidLayer2 w12: v5(1180,3245) 1400,3245 1410,3255 J1.1@1410,3305
GP1_1: R5.2 U1.16 | length 512.9
  Top Layer w10: v1(603.6,2953.6) v1@606.4,2950.81
  Top Layer w13.75: v1@606.4,2950.81 U1.16@693.37,2950.81
  Top Layer w24: R5.2@540,2558 v1(540,2620)
  MidLayer2 w24: v1(540,2620) 540,2890 v1(603.6,2953.6)
GP1_2: R6.1 U1.19 | length 439.1
  Top Layer w13.75: v1(595.96,2835.96) 634.04,2874.04 U1.19@693.37,2874.04
  Top Layer w32: R6.1@620,2560 v1(620,2620) v1(620,2660)
  MidLayer2 w32: v1(595.96,2835.96) 620,2811.93 v1(620,2660) v1(620,2620)
GP2_1: R11.1 U2.16 | length 489.7
  Top Layer w13: v1(2110,2940) 2118.7,2948.7 U2.16@2203.39,2948.7
  Top Layer w24: 2060,2568 v1(2060,2620)
  MidLayer2 w24: v1(2060,2620) 2060,2890 v1(2110,2940)
GP2_2: R12.2 U2.19 | length 412.8
  Top Layer w13.75: v1(2110,2830) 2120,2830 2161.93,2871.93 U2.19@2203.39,2871.93
  Top Layer w32: R12.2@2110,2568 v1(2110,2620) v1(2110,2660)
  MidLayer2 w32: v1(2110,2620) v1(2110,2660) v1(2110,2830)
IS1_H: C21.2 R3.1 U1.4 | length 258.6
  Top Layer w10: U1.4@913.84,2925.22 1001.67,2925.22 1033.6,2893.29 C21.2@1033.6,2861.29 1039.89,2855 1061.89,2855 1083.6,2833.29 R3.1@1115.6,2833.29
IS1_L: C21.1 R4.1 U1.3 | length 283.4
  Top Layer w10: U1.3@913.84,2899.63 975.37,2899.63 1000,2875 1000,2825 1010,2815 1023.89,2815 C21.1@1033.6,2805.29 1043.89,2795 1065,2795 1080,2780 1108.89,2780 R4.1@1115.6,2773.29
IS2_H: C22.2 R9.1 U2.4 | length 195.4
  Top Layer w10: U2.4@2423.86,2923.11 2518.11,2923.11 2524.81,2929.81 C22.2@2553.62,2929.81 2613.62,2929.81 R9.1@2615.62,2931.81
IS2_L: C22.1 R10.1 U2.3 | length 202.4
  Top Layer w10: U2.3@2423.86,2897.52 2497.91,2897.52 2521.62,2873.81 C22.1@2553.62,2873.81 2613.62,2873.81 R10.1@2615.62,2871.81
NetC1_2: C1.2 R1.2
NetC13_2: C13.2 R7.2
NetC19_1: C19.1 R35.2 | length 65
  Top Layer w13.7: C19.1@502,2785 R35.2@502,2850
NetC19_2: C19.2 D1.1 U1.20 | length 400.7
  Top Layer w13.7: C19.2@558,2785 605,2785 625,2805 625,2825 648.44,2848.44 U1.20@693.37,2848.44
  Top Layer w24: D1.1@420,2804.88 420,2755 430,2745 550,2745 558,2753 C19.2@558,2785
NetC20_1: C20.1 R36.2 | length 65
  Top Layer w16: C20.1@2002,2790 R36.2@2002,2855
NetC20_2: C20.2 D2.1 U2.20 | length 408.2
  Top Layer w13.75: C20.2@2058,2790 2115,2790 2171.34,2846.34 U2.20@2203.39,2846.34
  Top Layer w24: D2.1@1920,2805 1920,2750 1930,2740 2045,2740 2058,2753 C20.2@2058,2790
NetC25_1: C25.1 R29.2 U1.8 | length 305.5
  Top Layer w10: U1.8@913.84,3027.58 955.71,3027.58 1061.42,3133.29 R29.2@1115.6,3133.29 C25.1@1115.6,3193.29
NetC28_1: C28.1 R20.1 U1.5 | length 647.9
  Top Layer w10: U1.5@913.84,2950.81 1019.19,2950.81 v1(1060,2910) 1076.71,2893.29 C28.1@1115.6,2893.29 ; v1(1420,2890) 1425,2885 R20.1@1472,2885
  Bottom Layer w10: v1(1060,2910) 1400,2910 v1(1420,2890)
NetC30_1: C30.1 R21.1 U2.5 | length 269.6
  Top Layer w10: U2.5@2423.86,2948.7 2510.51,2948.7 2553.62,2991.81 R21.1@2615.62,2991.81 C30.1@2615.62,3051.81
NetC31_1: C31.1 C33.2 R31.1 R32.1 R33.1 U1.10 | length 1096.7
  Top Layer w10: C33.2@250,2968 318,2968 320,2970 ; R33.1@320,2896.5 R33.1@320,2898 320,2970 ; v1(335,3045) 320,3030 320,2970 ; C31.1@825.6,3163.6 883.6,3163.6 ; R31.1@881.6,3223.6 881.6,3165.6 883.6,3163.6 ; U1.10@913.84,3078.76 913.84,3161.84 915.6,3163.6 ; R32.1@943.6,3165.29 917.29,3165.29 915.6,3163.6 ; 883.6,3163.6 915.6,3163.6
  Bottom Layer w10: v1(335,3045) 355,3065 665,3065 720,3120 v1@910,3120
  other v1: 915,3120
NetC32_1: C32.1 R31.2 | length 74
  Top Layer w10: C32.1@751.6,3223.6 R31.2@825.6,3223.6
NetC33_1: C33.1 R37.1 | length 69
  Top Layer w10: R37.1@250,2843 C33.1@250,2912
NetL1_1: L1.1 R2.2 R4.2 | length 1722.7
  Top Layer w10: R4.2@1171.6,2773.29 1216.71,2773.29 v1(1220,2770)
  MidLayer2 w10: v1(1220,2770) 1220,2772 1240,2792 1448,2792 1672,2568 1672,1642 1620,1590 1530,1590 v1(1510,1610)
NetL2_1: L2.1 R8.2 R10.2 | length 1843.6
  Top Layer w10: R10.2@2671.62,2871.81 2718.19,2871.81 v1(2720,2870)
  MidLayer2 w10: v1(2720,2870) 2740,2890 3000,2890 3170,2720 3170,1645.46 3114.54,1590 3030,1590 v1(3010,1610)
NetQ1_4: Q1.4 R6.2 | length 797
  Top Layer w24: 620,1825 675,1770 Q1.4@675,1727.8
  Top Layer w40: 615,1825 R6.2@615,2502
NetQ2_4: Q2.4 R5.1 | length 1699.3
  Top Layer w24: v1(540,2450) R5.1@540,2502 ; Q2.4@1130,1508.78 1198.78,1508.78 v1(1200,1510)
  MidLayer2 w24: v1(540,2450) 540,1585 640,1485 1175,1485 v1(1200,1510)
NetQ3_4: Q3.4 R12.1 | length 797.1
  Top Layer w24: 2110,1834.09 2170,1774.09 Q3.4@2170,1732.8
  Top Layer w40: 2110,1834.09 R12.1@2110,2505
NetQ4_4: Q4.4 R11.2 | length 1703.8
  Top Layer w24: v1(2060,2450) 2060,2512 ; Q4.4@2635,1510 v1(2700,1510)
  MidLayer2 w24: v1(2060,2450) 2060,1565 2150,1475 2665,1475 v1(2700,1510)
NetR13_1: R13.1 R15.2 U1.2 | length 321.1
  Top Layer w10: U1.2@913.84,2874.04 960.96,2874.04 980,2855 980,2796.89 1023.6,2753.29 1043.6,2753.29 1051.6,2745.29 R13.1@1051.6,2713.29 R15.2@1115.6,2713.29
NetR14_1: R14.1 R16.2 U2.2 | length 276.7
  Top Layer w10: U2.2@2423.86,2871.93 2493.5,2871.93 2553.62,2811.81 R16.2@2615.62,2811.81 R14.1@2615.62,2751.81
NetR22_1: R22.1 R26.2 U1.13 | length 441.5
  Top Layer w10: R22.1@400,3048 390,3058 390,3080 v1(420,3110) ; R26.2@563.6,3165.29 563.6,3103.6 639.63,3027.58 U1.13@693.37,3027.58
  MidLayer2 w10: v1(420,3110) v1@560,3110
  other v1: 565,3110
NetR23_1: R23.1 R28.2 U2.13 | length 264.9
  Top Layer w10: R23.1@2038,3160 2088,3160 R28.2@2090,3162 2090,3090 2154.53,3025.47 U2.13@2203.39,3025.47
NetR25_2: R25.2 U1.12 | length 164.1
  Top Layer w10: R25.2@623.6,3165.29 623.6,3083.6 654.04,3053.17 U1.12@693.37,3053.17
NetR27_2: R27.2 U2.12 | length 159.1
  Top Layer w10: R27.2@2150,3162 2150,3060 2158.94,3051.06 U2.12@2203.39,3051.06
NetR33_2: R33.2 R34.2 R37.2 | length 348.5
  Top Layer w10: R37.2@250,2787 318,2787 320,2785 ; R33.2@320,2833.5 320,2785 ; R34.2@330,2560 v4(330,2635) 330,2665 320,2675 320,2785
RES: C27.1 U1.14 U2.14 | length 2550.2
  Top Layer w10: U1.14@693.37,3001.99 623.6,3001.99 503.6,3121.99 C27.1@503.6,3165.29 454.71,3165.29 440,3180 440,3340 495,3395 1720,3395 1900,3215 v1(1900,3065) ; v1(2130,3010) 2140.12,2999.88 U2.14@2203.39,2999.88
  Bottom Layer w10: v1(1900,3065) 2075,3065 v1(2130,3010)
